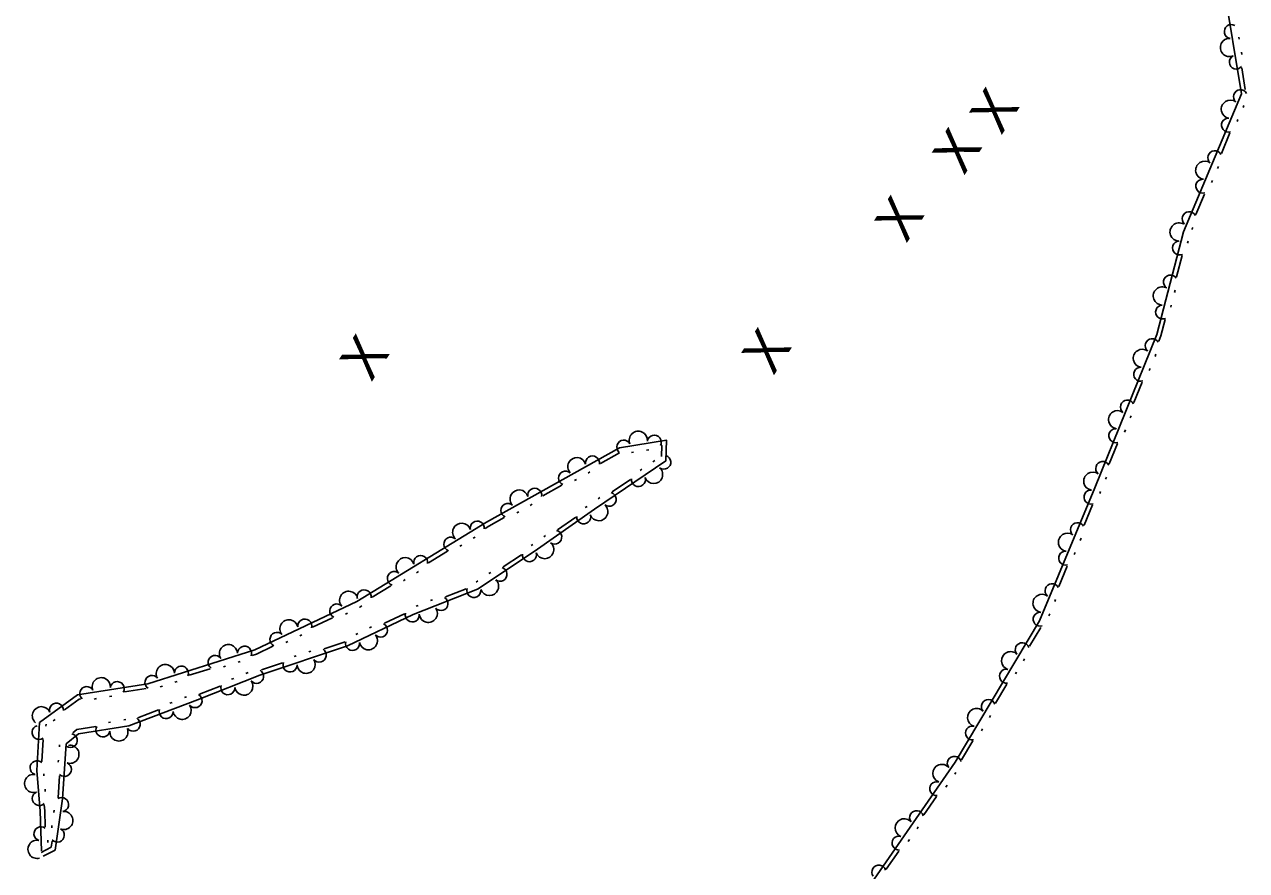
# Model space of a CAD drawing. Extents: x 2030130 to 2036320, y 723205 to 762423.
# Drawn here: x 2032314.4 to 2032541.6, y 759665.4 to 759822.6 of the extents above; entities that cross this region are included whole.
import ezdxf

# ---------------------------------------------------------------- set-up
doc = ezdxf.new("R2010")
doc.units = 0
doc.layers.add('Draft_Station Tics Major', color=7, linetype='Continuous')

msp = doc.modelspace()

# ---------------------------------------------------------------- linework, layer by layer
at = {"layer": 'Draft_Station Tics Major'}
for points in [[(2032537.4, 759829.61), (2032540.67, 759809.71), (2032529.91, 759784.06), (2032524.9, 759764.99), (2032513.4, 759736.48), (2032503.12, 759711.77), (2032487.41, 759685.49), (2032464, 759651.69), (2032439.01, 759613.41), (2032424.48, 759594.71)], [(2032540.18, 759820.28), (2032540.25, 759819.88)], [(2032540.65, 759817.45), (2032540.71, 759817.04)], [(2032540.71, 759814.55), (2032541.37, 759810.5)], [(2032541.12, 759807.58), (2032540.96, 759807.2)], [(2032540.01, 759804.94), (2032539.85, 759804.56)], [(2032538.52, 759802.45), (2032536.93, 759798.66)], [(2032536.36, 759796.23), (2032536.2, 759795.86)], [(2032535.25, 759793.59), (2032535.09, 759793.21)], [(2032533.76, 759791.1), (2032532.17, 759787.32)], [(2032531.6, 759784.89), (2032531.44, 759784.51)], [(2032530.73, 759782.34), (2032530.63, 759781.95)], [(2032529.61, 759779.67), (2032528.56, 759775.7)], [(2032528.34, 759773.22), (2032528.23, 759772.82)], [(2032527.61, 759770.44), (2032527.5, 759770.05)], [(2032526.48, 759767.77), (2032525.68, 759764.74), (2032525.29, 759763.75)], [(2032524.74, 759761.31), (2032524.59, 759760.93)], [(2032523.67, 759758.65), (2032523.52, 759758.27)], [(2032522.22, 759756.14), (2032520.68, 759752.34)], [(2032520.14, 759749.9), (2032519.99, 759749.52)], [(2032519.07, 759747.24), (2032518.91, 759746.86)], [(2032317.89, 759668.01), (2032320.16, 759669.17), (2032321.49, 759678.7), (2032322.21, 759688.9), (2032324.51, 759690.78), (2032333.82, 759692.24), (2032346.6, 759697.1), (2032358.18, 759701.67), (2032374.51, 759707.14), (2032386.68, 759712.93), (2032398.66, 759717.66), (2032409.21, 759724.66), (2032420.39, 759732.5), (2032433.64, 759741.49), (2032433.77, 759745.35), (2032425.03, 759743.92), (2032400.35, 759730.09), (2032376.22, 759715.39), (2032357.24, 759706.35), (2032337.39, 759700.09), (2032324.29, 759697.99), (2032317.25, 759692.86), (2032316.75, 759683.98), (2032317.38, 759676.4), (2032317.6, 759668.99)], [(2032432.84, 759742.34), (2032432.91, 759744.38), (2032432.85, 759744.37)], [(2032517.61, 759744.73), (2032516.08, 759740.93)], [(2032425.07, 759743.01), (2032421.5, 759741)], [(2032427.66, 759743.1), (2032427.25, 759743.04)], [(2032430.49, 759743.57), (2032430.09, 759743.5)], [(2032431.25, 759741.35), (2032431.59, 759741.58)], [(2032419.55, 759739.44), (2032419.19, 759739.24)], [(2032428.87, 759739.74), (2032429.21, 759739.97)], [(2032414.34, 759736.99), (2032410.77, 759734.98)], [(2032417.05, 759738.04), (2032416.69, 759737.84)], [(2032423.67, 759735.72), (2032427.07, 759738.02)], [(2032515.54, 759738.49), (2032515.39, 759738.11)], [(2032514.46, 759735.82), (2032514.3, 759735.44)], [(2032408.82, 759733.43), (2032408.46, 759733.22)], [(2032418.69, 759732.81), (2032419.03, 759733.04)], [(2032421.07, 759734.45), (2032421.41, 759734.68)], [(2032512.98, 759733.32), (2032511.4, 759729.54)], [(2032403.61, 759730.97), (2032400.77, 759729.38), (2032400.07, 759728.96)], [(2032406.31, 759732.02), (2032405.96, 759731.82)], [(2032413.55, 759728.7), (2032416.91, 759731.06)], [(2032395.73, 759725.83), (2032395.38, 759725.62)], [(2032398.19, 759727.33), (2032397.84, 759727.12)], [(2032408.61, 759725.74), (2032408.95, 759725.98)], [(2032410.96, 759727.39), (2032411.3, 759727.63)], [(2032510.84, 759727.11), (2032510.68, 759726.73)], [(2032393.07, 759724.69), (2032389.57, 759722.56)], [(2032403.4, 759721.79), (2032406.82, 759724.06)], [(2032509.73, 759724.46), (2032509.57, 759724.08)], [(2032508.25, 759721.96), (2032506.68, 759718.18)], [(2032385.23, 759719.43), (2032384.87, 759719.22)], [(2032387.68, 759720.93), (2032387.33, 759720.71)], [(2032398.39, 759718.96), (2032398.73, 759719.19)], [(2032400.78, 759720.55), (2032401.12, 759720.77)], [(2032382.56, 759718.29), (2032379.06, 759716.16)], [(2032392.71, 759716.2), (2032396.53, 759717.7)], [(2032377.17, 759714.53), (2032376.8, 759714.31), (2032376.71, 759714.26)], [(2032387.22, 759714.47), (2032387.6, 759714.62)], [(2032389.89, 759715.52), (2032390.28, 759715.68)], [(2032506.11, 759715.75), (2032505.95, 759715.37)], [(2032371.72, 759712.34), (2032368.01, 759710.58)], [(2032374.49, 759713.2), (2032374.12, 759713.03)], [(2032381.37, 759711.31), (2032385.07, 759713.08)], [(2032505.01, 759713.1), (2032504.85, 759712.72)], [(2032378.6, 759710.45), (2032378.97, 759710.63)], [(2032503.35, 759710.56), (2032501.25, 759707.04)], [(2032363.38, 759707.91), (2032363.01, 759707.74)], [(2032365.97, 759709.15), (2032365.6, 759708.97)], [(2032370.16, 759706.55), (2032374.04, 759707.85)], [(2032376.01, 759709.21), (2032376.38, 759709.39)], [(2032360.61, 759707.05), (2032357.54, 759705.59), (2032356.76, 759705.34)], [(2032364.58, 759705.11), (2032364.97, 759705.24)], [(2032367.3, 759706.03), (2032367.69, 759706.16)], [(2032351.8, 759703.35), (2032351.41, 759703.22)], [(2032354.54, 759704.21), (2032354.15, 759704.09)], [(2032358.49, 759702.64), (2032362.38, 759703.94)], [(2032500.34, 759704.72), (2032500.13, 759704.36)], [(2032348.94, 759702.87), (2032345.03, 759701.64)], [(2032352.95, 759700.93), (2032353.33, 759701.08)], [(2032355.61, 759701.99), (2032356, 759702.14)], [(2032498.87, 759702.25), (2032498.66, 759701.9)], [(2032337.08, 759699.21), (2032333.03, 759698.56)], [(2032340.07, 759699.64), (2032339.68, 759699.52)], [(2032342.81, 759700.51), (2032342.42, 759700.38)], [(2032346.99, 759698.14), (2032350.81, 759699.64)], [(2032497.04, 759700), (2032494.94, 759696.48)], [(2032324.93, 759697.26), (2032324.61, 759697.21), (2032321.87, 759695.22)], [(2032327.83, 759697.31), (2032327.42, 759697.24)], [(2032330.66, 759697.76), (2032330.26, 759697.7)], [(2032341.49, 759696.47), (2032341.88, 759696.62)], [(2032344.18, 759697.5), (2032344.56, 759697.64)], [(2032335.51, 759693.76), (2032339.34, 759695.22)], [(2032494.03, 759694.16), (2032493.81, 759693.8)], [(2032318.46, 759692.59), (2032318.44, 759692.18)], [(2032320.12, 759693.44), (2032319.79, 759693.19)], [(2032323.4, 759690.94), (2032324.17, 759691.56), (2032327.68, 759692.11)], [(2032330.05, 759692.89), (2032330.45, 759692.96)], [(2032332.89, 759693.34), (2032333.29, 759693.4)], [(2032492.55, 759691.69), (2032492.34, 759691.34)], [(2032317.89, 759689.74), (2032317.66, 759685.65)], [(2032490.73, 759689.44), (2032488.62, 759685.92)], [(2032320.93, 759688.33), (2032320.96, 759688.74)], [(2032320.73, 759685.47), (2032320.76, 759685.88)], [(2032318.03, 759683.34), (2032318.07, 759682.93)], [(2032320.68, 759678.89), (2032320.97, 759682.98)], [(2032487.59, 759683.58), (2032487.35, 759683.24)], [(2032318.27, 759680.48), (2032318.3, 759680.07)], [(2032485.95, 759681.22), (2032485.72, 759680.88)], [(2032483.98, 759679.1), (2032481.64, 759675.72)], [(2032318.1, 759677.59), (2032318.2, 759676.45), (2032318.29, 759673.45)], [(2032319.89, 759676.16), (2032319.95, 759676.57)], [(2032319.5, 759673.32), (2032319.55, 759673.72)], [(2032480.58, 759673.47), (2032480.35, 759673.13)], [(2032478.95, 759671.11), (2032478.71, 759670.77)], [(2032317.52, 759668.74), (2032319.41, 759669.71), (2032319.56, 759670.82)], [(2032318.77, 759671), (2032318.78, 759670.59)], [(2032476.97, 759668.98), (2032474.64, 759665.61)]]:
    msp.add_lwpolyline(points, dxfattribs=at)
for centre, radius, start, end in [((2032538.77, 759821.3), 1.3, 60.114, 260.9105), ((2032538.42, 759818.33), 1.69, 85.3092, 293.3817), ((2032539.7, 759815.63), 1.3, 117.7804, 318.577), ((2032540.46, 759809.19), 1.3, 28.0058, 228.8024), ((2032538.59, 759806.86), 1.69, 53.2011, 261.2736), ((2032538.24, 759803.9), 1.3, 85.6723, 286.4688), ((2032535.7, 759797.85), 1.3, 28.0058, 228.8024), ((2032533.83, 759795.52), 1.69, 53.2011, 261.2736), ((2032533.48, 759792.55), 1.3, 85.6723, 286.4688), ((2032530.94, 759786.5), 1.3, 28.0058, 228.8024), ((2032529.06, 759784.05), 1.69, 61.2468, 269.3193), ((2032529.13, 759781.07), 1.3, 93.718, 294.5145), ((2032527.46, 759774.72), 1.3, 36.0515, 236.8481), ((2032525.94, 759772.15), 1.69, 61.2468, 269.3193), ((2032526, 759769.17), 1.3, 93.718, 294.5145), ((2032522.23, 759760.56), 1.69, 53.9972, 262.0697), ((2032524.06, 759762.91), 1.3, 28.8019, 229.5985), ((2032521.92, 759757.59), 1.3, 86.4684, 287.2649), ((2032517.63, 759749.15), 1.69, 53.9972, 262.0697), ((2032519.46, 759751.5), 1.3, 28.8019, 229.5985), ((2032428.54, 759745.33), 1.69, 355.2507, 203.3232), ((2032431.51, 759744.98), 1.3, 330.0554, 170.852), ((2032517.31, 759746.18), 1.3, 86.4684, 287.2649), ((2032425.84, 759744.05), 1.3, 27.7219, 228.5184), ((2032417.12, 759740.43), 1.69, 15.2365, 223.309), ((2032420.02, 759741.11), 1.3, 350.0413, 190.8378), ((2032433.3, 759741.26), 1.3, 232.595, 73.3916), ((2032415.01, 759738.31), 1.3, 47.7077, 248.5043), ((2032431.38, 759738.97), 1.69, 200.1238, 48.1963), ((2032513.02, 759737.74), 1.69, 53.9972, 262.0697), ((2032514.86, 759740.09), 1.3, 28.8019, 229.5985), ((2032428.55, 759738.03), 1.3, 174.9285, 15.7251), ((2032406.39, 759734.41), 1.69, 15.2365, 223.309), ((2032409.29, 759735.1), 1.3, 350.0413, 190.8378), ((2032423.12, 759734.35), 1.3, 232.595, 73.3916), ((2032512.69, 759734.77), 1.3, 85.8439, 286.6404), ((2032404.28, 759732.29), 1.3, 47.7077, 248.5043), ((2032421.2, 759732.06), 1.69, 200.1238, 48.1963), ((2032398.6, 759729.02), 1.3, 352.1124, 192.9089), ((2032418.39, 759731.09), 1.3, 175.809, 16.6056), ((2032395.72, 759728.23), 1.69, 17.3076, 225.3801), ((2032413.01, 759727.33), 1.3, 233.4755, 74.272), ((2032508.31, 759726.38), 1.69, 53.3727, 261.4452), ((2032510.17, 759728.72), 1.3, 28.1774, 228.974), ((2032393.69, 759726.03), 1.3, 49.7788, 250.5754), ((2032411.14, 759725.01), 1.69, 201.0043, 49.0767), ((2032385.21, 759721.83), 1.69, 17.3076, 225.3801), ((2032388.09, 759722.62), 1.3, 352.1124, 192.9089), ((2032408.3, 759724.05), 1.3, 174.3175, 15.1141), ((2032507.97, 759723.42), 1.3, 85.8439, 286.6404), ((2032402.83, 759720.43), 1.3, 231.984, 72.7806), ((2032383.19, 759719.63), 1.3, 49.7788, 250.5754), ((2032400.89, 759718.16), 1.69, 199.5128, 47.5853), ((2032374.71, 759715.58), 1.69, 11.4169, 219.4894), ((2032377.58, 759716.22), 1.3, 352.1124, 192.9089), ((2032397.97, 759717.39), 1.3, 162.3104, 3.107), ((2032503.59, 759715.02), 1.69, 53.3727, 261.4452), ((2032505.45, 759717.36), 1.3, 28.1774, 228.974), ((2032372.48, 759713.61), 1.3, 43.8881, 244.6847), ((2032391.87, 759714.98), 1.3, 219.9769, 60.7735), ((2032366.55, 759710.79), 1.3, 346.2216, 187.0182), ((2032386.53, 759712.86), 1.3, 166.2305, 7.027), ((2032389.5, 759713.16), 1.69, 187.5057, 35.5782), ((2032503.24, 759712.06), 1.3, 85.8439, 286.6404), ((2032363.61, 759710.29), 1.69, 11.4169, 219.4894), ((2032380.61, 759710.04), 1.3, 223.8969, 64.6935), ((2032361.37, 759708.32), 1.3, 43.8881, 244.6847), ((2032375.43, 759707.57), 1.3, 166.2305, 7.027), ((2032378.37, 759708.07), 1.69, 191.4258, 39.4982), ((2032499.91, 759706.4), 1.3, 19.9008, 220.6974), ((2032349.87, 759704.03), 1.3, 35.9595, 236.7561), ((2032352.36, 759705.67), 1.69, 3.4883, 211.5608), ((2032355.34, 759705.76), 1.3, 338.293, 179.0896), ((2032369.25, 759705.38), 1.3, 216.9329, 57.7294), ((2032497.74, 759704.36), 1.69, 45.0961, 253.1686), ((2032340.62, 759701.97), 1.69, 3.4883, 211.5608), ((2032343.61, 759702.05), 1.3, 338.293, 179.0896), ((2032363.8, 759703.56), 1.3, 159.2664, 0.063), ((2032366.79, 759703.69), 1.69, 184.4617, 32.5342), ((2032328.72, 759699.53), 1.69, 355.068, 203.1405), ((2032338.13, 759700.32), 1.3, 35.9595, 236.7561), ((2032357.59, 759701.44), 1.3, 219.9951, 60.7917), ((2032496.97, 759701.48), 1.3, 77.5673, 278.3638), ((2032326.01, 759698.26), 1.3, 27.5392, 228.3358), ((2032331.68, 759699.17), 1.3, 329.8727, 170.6693), ((2032352.25, 759699.33), 1.3, 162.3287, 3.1253), ((2032355.22, 759699.63), 1.69, 187.524, 35.5964), ((2032320.39, 759695.16), 1.3, 356.8082, 197.6047), ((2032343.76, 759695.14), 1.69, 186.7896, 34.8621), ((2032346.15, 759696.93), 1.3, 219.2608, 60.0574), ((2032493.6, 759695.84), 1.3, 19.9008, 220.6974), ((2032317.59, 759694.13), 1.69, 22.0034, 230.0759), ((2032340.78, 759694.89), 1.3, 161.5944, 2.3909), ((2032491.42, 759693.8), 1.69, 45.0961, 253.1686), ((2032317.14, 759691.02), 1.3, 105.2121, 306.0086), ((2032329.02, 759691.49), 1.3, 149.6524, 350.4489), ((2032331.99, 759691.12), 1.69, 174.8477, 22.9201), ((2032334.65, 759692.55), 1.3, 219.2608, 60.0574), ((2032490.66, 759690.92), 1.3, 77.5673, 278.3638), ((2032322.97, 759689.52), 1.3, 237.6344, 78.431), ((2032322.89, 759686.96), 1.69, 251.9452, 100.0177), ((2032316.77, 759684.47), 1.3, 47.5456, 248.3422), ((2032321.87, 759684.15), 1.3, 226.75, 67.5465), ((2032484.97, 759683.4), 1.69, 41.2494, 249.3219), ((2032487.28, 759685.29), 1.3, 16.0542, 216.8507), ((2032316.13, 759681.54), 1.69, 80.7171, 288.7896), ((2032484.01, 759680.57), 1.3, 73.7206, 274.5172), ((2032317.18, 759678.75), 1.3, 113.1883, 313.9849), ((2032321.34, 759677.62), 1.3, 280.5045, 121.3011), ((2032321.75, 759674.66), 1.69, 248.0333, 96.1058), ((2032480.27, 759675.18), 1.3, 16.0542, 216.8507), ((2032317.5, 759672.19), 1.3, 52.4919, 253.2885), ((2032477.96, 759673.29), 1.69, 41.2494, 249.3219), ((2032320.55, 759671.93), 1.3, 222.8381, 63.6346), ((2032477, 759670.46), 1.3, 73.7206, 274.5172), ((2032316.77, 759669.3), 1.69, 77.6872, 285.7597), ((2032473.26, 759665.07), 1.3, 16.0542, 216.8507)]:
    msp.add_arc(centre, radius, start, end, dxfattribs=at)

# ---------------------------------------------------------------- texts
for p in [(2032495.98, 759801.89), (2032489.04, 759794.41), (2032478.33, 759781.8), (2032378.89, 759756.02), (2032453.63, 759757.22)]:
    msp.add_text('X', height=7.38, rotation=57.2106, dxfattribs=at).set_placement(p)

doc.saveas('drawing.dxf')
